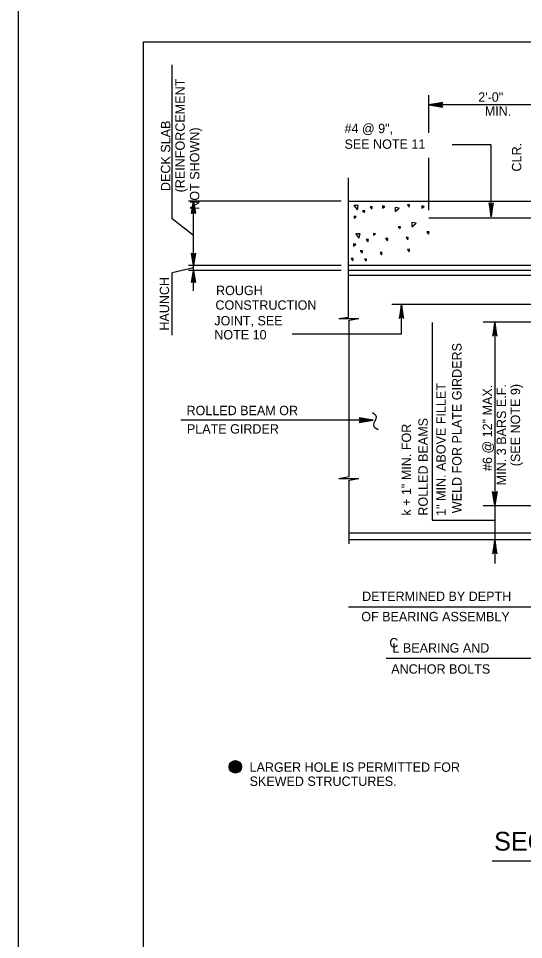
# Model space of a CAD drawing. Extents: x 640009 to 641706, y 298547 to 299735.
# Drawn here: x 640009.5 to 640171.1, y 298839.2 to 299133.7 of the extents above; entities that cross this region are included whole.
import ezdxf

# ---------------------------------------------------------------- set-up
doc = ezdxf.new("R2010")
doc.units = 0
doc.layers.add('1', color=7, linetype='Continuous')
doc.layers.add('PLT-BNDY', color=7, linetype='Continuous')

msp = doc.modelspace()

# ---------------------------------------------------------------- linework, layer by layer
at = {"layer": '1'}
for p, q in [((640049.47, 298562.17), (640049.47, 299126.17)), ((640049.47, 299126.17), (640835.47, 299126.17)), ((640049.47, 298562.17), (640049.47, 299126.17)), ((640049.47, 299126.17), (640835.47, 299126.17)), ((640058.68, 299069.63), (640058.68, 299118.8)), ((640140.79, 299097.11), (640140.79, 299109.18)), ((640238.79, 299106.08), (640140.79, 299106.08)), ((640160.67, 299093.22), (640148.22, 299093.22)), ((640160.67, 299070.22), (640160.67, 299093.22)), ((640140.79, 299072.41), (640140.79, 299089.06)), ((640115.04, 299038.22), (640115.04, 299082.72)), ((640112.73, 299075.22), (640063.83, 299075.22)), ((640065.45, 299046.55), (640065.45, 299075.22)), ((640115.04, 299075.22), (640238.79, 299075.22)), ((640065.45, 299064.29), (640058.68, 299069.63)), ((640140.79, 299069.97), (640234.67, 299069.97)), ((640065.45, 299053.95), (640058.68, 299052.3)), ((640112.73, 299054.72), (640063.83, 299054.72)), ((640180.17, 299054.72), (640115.04, 299054.72)), ((640058.68, 299032.45), (640058.68, 299052.3)), ((640112.73, 299053.1), (640063.83, 299053.1)), ((640180.92, 299053.1), (640115.04, 299053.1)), ((640181.67, 299051.47), (640115.04, 299051.47)), ((640183.04, 299042.22), (640128.97, 299042.22)), ((640132.04, 299032.72), (640132.04, 299042.22)), ((640111.92, 299037.72), (640115.04, 299038.22)), ((640111.92, 299037.72), (640118.42, 299037.72)), ((640115.17, 299037.72), (640115.17, 299037.72)), ((640115.29, 299037.22), (640118.42, 299037.72)), ((640115.29, 298987.22), (640115.29, 299037.22)), ((640141.79, 299036.48), (640141.79, 298973.28)), ((640190.42, 299036.6), (640158.12, 299036.6)), ((640161.85, 299036.6), (640161.85, 298959.47)), ((640132.04, 299032.72), (640097.07, 299032.72)), ((640123, 299005.22), (640061.38, 299005.22)), ((640111.92, 298986.6), (640115.29, 298987.22)), ((640111.92, 298986.6), (640118.42, 298986.6)), ((640115.17, 298986.6), (640115.17, 298986.6)), ((640115.29, 298986.1), (640118.42, 298986.6)), ((640115.29, 298965.72), (640115.29, 298986.1)), ((640158.12, 298977.97), (640215.42, 298977.97)), ((640141.79, 298973.28), (640161.85, 298973.28)), ((640182.01, 298969.1), (640115.29, 298969.1)), ((640219.04, 298966.97), (640115.29, 298966.97)), ((640184.67, 298945.47), (640115.04, 298945.47)), ((640127.12, 298929.22), (640179.3, 298929.22)), ((640161, 298864.4), (640293.29, 298864.4))]:
    msp.add_line(p, q, dxfattribs=at)
for points in [[(640145.04, 299106.62), (640144.86, 299106.3), (640140.79, 299106.08), (640145.04, 299106.62), (640145.25, 299106.81), (640140.79, 299106.08), (640144.86, 299105.88), (640145.02, 299105.58), (640140.79, 299106.08), (640145.25, 299105.36), (640145.02, 299105.58)], [(640064.95, 299071.47), (640065.33, 299071.6), (640065.45, 299075.22), (640064.95, 299071.47), (640064.83, 299071.35), (640065.45, 299075.22), (640065.7, 299071.6), (640065.95, 299071.47), (640065.45, 299075.22), (640066.08, 299071.35), (640065.95, 299071.47)], [(640160.15, 299074.51), (640160.46, 299074.34), (640160.69, 299070.27), (640160.15, 299074.51), (640159.96, 299074.72), (640160.69, 299070.27), (640160.88, 299074.34), (640161.19, 299074.49), (640160.69, 299070.27), (640161.41, 299074.72), (640161.19, 299074.49)], [(640065.95, 299058.47), (640065.7, 299058.35), (640065.45, 299054.72), (640065.95, 299058.47), (640066.08, 299058.6), (640065.45, 299054.72), (640065.33, 299058.35), (640065.08, 299058.47), (640065.45, 299054.72), (640064.83, 299058.6), (640065.08, 299058.47)], [(640064.95, 299049.35), (640065.33, 299049.47), (640065.45, 299053.1), (640064.95, 299049.35), (640064.83, 299049.22), (640065.45, 299053.1), (640065.7, 299049.47), (640065.95, 299049.35), (640065.45, 299053.1), (640066.08, 299049.22), (640065.95, 299049.35)], [(640132.57, 299037.93), (640132.25, 299038.11), (640132.03, 299042.18), (640132.57, 299037.93), (640132.75, 299037.72), (640132.03, 299042.18), (640131.83, 299038.11), (640131.53, 299037.95), (640132.03, 299042.18), (640131.3, 299037.72), (640131.53, 299037.95)], [(640162.39, 299032.35), (640162.07, 299032.53), (640161.85, 299036.6), (640162.39, 299032.35), (640162.57, 299032.14), (640161.85, 299036.6), (640161.65, 299032.53), (640161.35, 299032.37), (640161.85, 299036.6), (640161.13, 299032.14), (640161.35, 299032.37)], [(640118.71, 299004.7), (640118.89, 299005.02), (640122.96, 299005.24), (640118.71, 299004.7), (640118.5, 299004.51), (640122.96, 299005.24), (640118.89, 299005.44), (640118.73, 299005.74), (640122.96, 299005.24), (640118.5, 299005.96), (640118.73, 299005.74)], [(640162.39, 298982.22), (640162.07, 298982.04), (640161.85, 298977.97), (640162.39, 298982.22), (640162.57, 298982.43), (640161.85, 298977.97), (640161.65, 298982.04), (640161.35, 298982.2), (640161.85, 298977.97), (640161.13, 298982.43), (640161.35, 298982.2)], [(640162.39, 298962.73), (640162.07, 298962.9), (640161.85, 298966.97), (640162.39, 298962.73), (640162.57, 298962.52), (640161.85, 298966.97), (640161.65, 298962.9), (640161.35, 298962.75), (640161.85, 298966.97), (640161.13, 298962.52), (640161.35, 298962.75)], [(640077.02, 298893.92), (640076.91, 298894.54), (640077.13, 298895.28), (640077.81, 298896.05), (640078.45, 298896.32), (640079.23, 298896.33), (640080.1, 298895.92), (640080.62, 298895.34), (640080.78, 298894.69), (640080.76, 298893.96), (640080.45, 298893.33), (640080.06, 298892.9), (640079.46, 298892.63), (640078.79, 298892.5), (640078.16, 298892.67), (640077.63, 298892.98), (640077.21, 298893.49), (640077.03, 298893.92), (640077.04, 298895.06), (640077.12, 298893.7), (640077.13, 298895.32), (640077.24, 298893.34), (640077.28, 298895.55), (640077.36, 298893.24), (640077.38, 298895.67), (640077.46, 298893.11), (640077.51, 298895.83), (640077.58, 298892.99), (640077.61, 298895.95), (640077.7, 298892.92), (640077.71, 298895.99), (640077.78, 298892.84), (640077.81, 298896.1), (640077.84, 298892.79), (640077.9, 298896.13), (640077.95, 298892.75), (640077.97, 298896.19), (640078.02, 298892.71), (640078.05, 298896.23), (640078.13, 298892.61), (640078.13, 298896.26), (640078.25, 298892.59), (640078.19, 298896.29), (640078.38, 298892.57), (640078.32, 298896.33), (640078.53, 298892.52), (640078.42, 298896.33), (640078.47, 298892.54), (640078.51, 298896.38), (640078.62, 298892.51), (640078.62, 298896.37), (640078.71, 298892.5), (640078.69, 298896.4), (640078.79, 298892.49), (640078.76, 298896.4), (640078.92, 298892.51), (640078.86, 298896.4), (640079.01, 298892.5), (640078.96, 298896.42), (640078.86, 298892.48), (640079.04, 298896.4), (640079.09, 298892.5), (640079.13, 298896.41), (640079.18, 298892.51), (640079.22, 298896.37), (640079.25, 298892.53), (640079.3, 298896.35), (640079.35, 298892.56), (640079.37, 298896.33), (640079.44, 298892.57), (640079.46, 298896.32), (640079.54, 298892.64), (640079.55, 298896.3), (640079.63, 298892.65), (640079.61, 298896.26), (640079.72, 298892.68), (640079.69, 298896.22), (640079.81, 298892.74), (640079.78, 298896.19), (640079.88, 298892.78), (640079.87, 298896.14), (640079.95, 298892.81), (640079.97, 298896.09), (640080.03, 298892.87), (640080.04, 298896.04), (640080.09, 298892.93), (640080.13, 298895.95), (640080.2, 298893.03), (640080.23, 298895.84), (640080.3, 298893.12), (640080.33, 298895.73), (640080.44, 298893.25), (640080.41, 298895.64), (640080.56, 298893.49), (640080.51, 298895.56), (640080.51, 298893.42), (640080.59, 298895.42), (640080.62, 298893.58), (640080.67, 298895.25), (640080.68, 298893.7), (640080.74, 298895.06)], [(640080.74, 298895.06), (640080.83, 298894.37), (640080.16, 298893.34), (640078.78, 298892.71), (640077.22, 298893.63), (640077.06, 298894.98), (640078.26, 298896.02), (640079.54, 298896.02), (640080.49, 298895.37), (640080.7, 298894.29), (640080.06, 298893.06), (640080.43, 298893.51), (640078.39, 298892.73), (640077.26, 298893.46), (640076.95, 298894.54), (640077.31, 298895.33), (640078.09, 298896), (640078.72, 298896.3), (640079.98, 298895.95)]]:
    msp.add_lwpolyline(points, dxfattribs=at)
for points in [[(640116.79, 299073.85), (640117.92, 299072.47), (640118.17, 299073.85)], [(640119.54, 299072.22), (640120.17, 299071.6), (640120.29, 299072.22)], [(640122.04, 299073.47), (640122.54, 299072.72), (640122.67, 299073.47)], [(640125.92, 299072.97), (640126.67, 299073.6), (640125.92, 299073.72)], [(640130.04, 299071.97), (640131.29, 299072.97), (640130.04, 299073.22)], [(640133.92, 299074.1), (640134.42, 299073.35), (640134.54, 299074.1)], [(640138.54, 299072.97), (640139.29, 299073.6), (640138.54, 299073.72)], [(640116.92, 299069.85), (640117.54, 299070.35), (640116.92, 299070.47)], [(640135.29, 299067.1), (640136.67, 299068.22), (640135.29, 299068.47)], [(640130.92, 299067.1), (640131.54, 299066.47), (640131.67, 299067.1)], [(640140.17, 299065.47), (640140.67, 299064.72), (640140.92, 299065.47)], [(640117.42, 299064.85), (640118.42, 299063.47), (640118.79, 299064.85)], [(640120.67, 299062.97), (640121.29, 299062.22), (640121.42, 299062.97)], [(640123.04, 299064.35), (640123.67, 299064.85), (640123.04, 299064.97)], [(640126.92, 299063.35), (640127.54, 299062.6), (640127.67, 299063.35)], [(640133.54, 299063.6), (640134.04, 299062.85), (640134.17, 299063.6)], [(640116.67, 299060.85), (640117.42, 299061.47), (640116.67, 299061.6)], [(640133.92, 299059.85), (640134.42, 299059.1), (640134.54, 299059.85)], [(640115.92, 299056.97), (640116.42, 299056.22), (640116.54, 299056.97)], [(640118.79, 299059.35), (640119.42, 299058.6), (640119.54, 299059.35)], [(640120.17, 299056.72), (640120.67, 299056.1), (640120.79, 299056.72)], [(640125.17, 299058.85), (640125.67, 299058.1), (640125.79, 299058.85)]]:
    msp.add_lwpolyline(points, close=True, dxfattribs=at)
msp.add_circle((640078.87, 298894.45), 2, dxfattribs=at)
msp.add_spline([(640122.76, 299007.75), (640123.92, 299006.39), (640123.01, 299003.62), (640124.51, 299002.25)], degree=3, dxfattribs=at)
at = {"layer": 'PLT-BNDY'}
msp.add_lwpolyline([(640009.47, 299141.17), (640850.47, 299141.17), (640850.47, 298547.17), (640009.47, 298547.17)], close=True, dxfattribs=at)

# ---------------------------------------------------------------- texts
at = {"layer": '1'}
for s, p in [('(REINFORCEMENT', (640062.69, 299078.07)), ('DECK SLAB', (640058.05, 299078.49)), ('   NOT SHOWN)', (640067.34, 299069.18)), ('CLR.', (640170.34, 299084.73)), ('HAUNCH', (640057.68, 299033.86)), ('WELD FOR PLATE GIRDERS', (640151.22, 298975.52)), ('1" MIN. ABOVE FILLET', (640146.15, 298974.68)), ('#6 @ 12" MAX.', (640160.99, 298989)), ('MIN. 3 BARS E.F.', (640165.47, 298984.45)), ('(SEE NOTE 9)', (640169.96, 298990.52)), ('k + 1" MIN. FOR', (640135.08, 298974.73)), ('ROLLED BEAMS', (640140.42, 298974.73))]:
    msp.add_text(s, height=3, rotation=90, dxfattribs=at).set_placement(p)
for s, height, p in [('2\'-0"', 3, (640156.57, 299107.04)), ('MIN.', 3, (640158.67, 299102.56)), ('#4 @ 9",', 3, (640113.79, 299097)), ('SEE NOTE 11', 3, (640113.79, 299092)), ('ROUGH', 3, (640072.69, 299045.23)), ('CONSTRUCTION', 3, (640072.51, 299040.55)), ('JOINT, SEE', 3, (640072.14, 299035.55)), ('NOTE 10', 3, (640072.14, 299031.06)), ('ROLLED BEAM OR', 3, (640063.25, 299006.85)), ('PLATE GIRDER', 3, (640063.38, 299000.97)), ('DETERMINED BY DEPTH', 3, (640119.42, 298947.47)), ('OF BEARING ASSEMBLY', 3, (640119.15, 298940.97)), ('C', 3, (640128.12, 298932.6)), ('L BEARING AND ', 3, (640129.12, 298930.97)), ('ANCHOR BOLTS', 3, (640128.74, 298924.22)), ('LARGER HOLE IS PERMITTED FOR', 3, (640083.42, 298892.85)), ('SKEWED STRUCTURES.', 3, (640083.42, 298888.35)), ('SECTION - POT BEARINGS', 6, (640161.66, 298867.67))]:
    msp.add_text(s, height=height, dxfattribs=at).set_placement(p)

doc.saveas('drawing.dxf')
